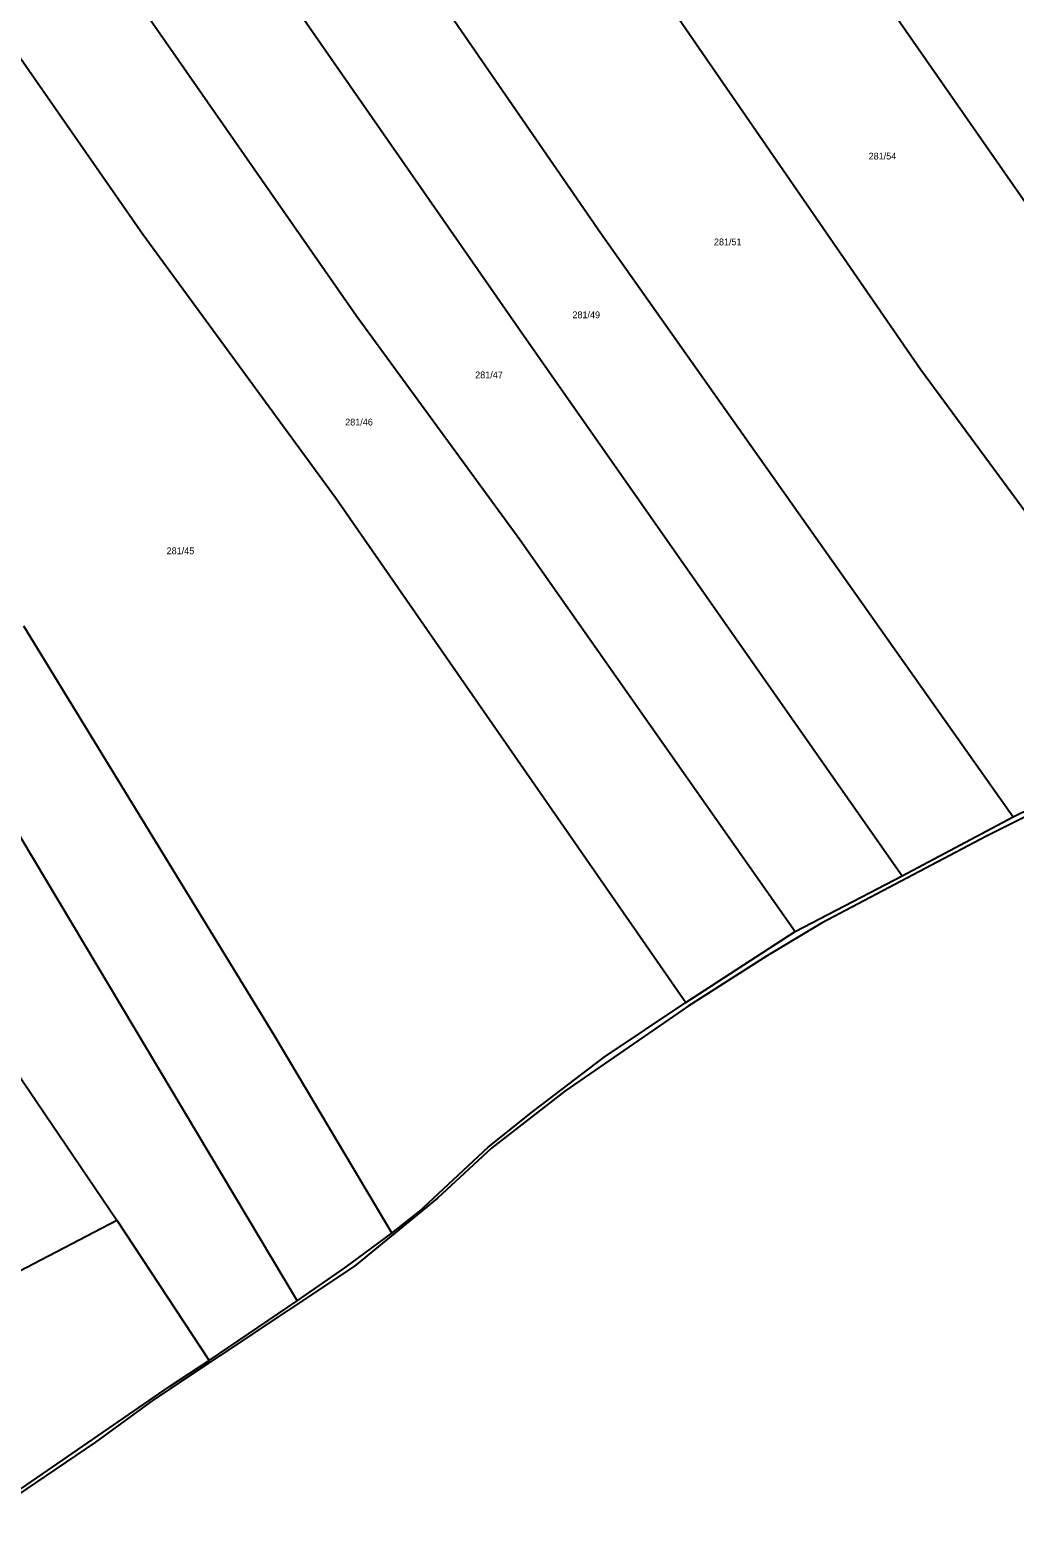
# Model space of a CAD drawing. Extents: x -779723 to -777378, y -1011169 to -1009297.
# Drawn here: x -778145.5 to -777897.6, y -1011100.8 to -1010721.1 of the extents above; entities that cross this region are included whole.
import ezdxf

# ---------------------------------------------------------------- set-up
doc = ezdxf.new("R2010")
doc.units = 0
doc.layers.add('KN_HRANICE', color=7, linetype='Continuous')
doc.layers.add('KN_PARCELY', color=7, linetype='Continuous')

msp = doc.modelspace()

# ---------------------------------------------------------------- linework, layer by layer
at = {"layer": 'KN_HRANICE'}
for p, q in [((-778087.99, -1010647.3), (-778001.85, -1010772.26)), ((-778115.74, -1010662.1), (-778021.13, -1010798.24)), ((-778143.85, -1010677.34), (-778063.35, -1010793.06)), ((-778173.03, -1010692.24), (-778117.21, -1010772.54)), ((-777935.33, -1010706.44), (-777864.34, -1010808.65)), ((-777983.83, -1010715.92), (-777921.4, -1010806.5)), ((-778117.21, -1010772.54), (-778068.65, -1010838.85)), ((-778001.85, -1010772.26), (-777898.07, -1010919.25)), ((-778063.35, -1010793.06), (-778022.29, -1010849.42)), ((-778021.13, -1010798.24), (-777926.01, -1010934.1)), ((-777921.4, -1010806.5), (-777893.7, -1010844.14)), ((-778068.65, -1010838.85), (-777980.49, -1010965.98)), ((-778022.29, -1010849.42), (-777952.91, -1010948.15)), ((-778147.23, -1010871.18), (-778084.18, -1010974.16)), ((-777898.07, -1010919.25), (-777855.82, -1010898.56)), ((-778156.55, -1010910.11), (-778078.29, -1011041.12)), ((-777893.68, -1010918.59), (-777904.75, -1010924.16)), ((-777926.01, -1010934.1), (-777898.07, -1010919.25)), ((-777904.75, -1010924.16), (-777946.29, -1010946.05)), ((-777952.91, -1010948.15), (-777926.01, -1010934.1)), ((-777980.49, -1010965.98), (-777952.91, -1010948.15)), ((-777946.29, -1010946.05), (-777960.11, -1010954.32)), ((-777960.11, -1010954.32), (-777979.84, -1010966.89)), ((-777979.84, -1010966.89), (-778010.92, -1010988.32)), ((-778001.04, -1010979.74), (-777980.49, -1010965.98)), ((-778084.18, -1010974.16), (-778054.46, -1011024.11)), ((-778150.99, -1010980.51), (-778123.71, -1011020.78)), ((-778018.96, -1010993.43), (-778001.04, -1010979.74)), ((-778010.92, -1010988.32), (-778029.41, -1011002.72)), ((-778030.19, -1011002.43), (-778018.96, -1010993.43)), ((-778047.71, -1011018.72), (-778030.19, -1011002.43)), ((-778029.41, -1011002.72), (-778042.94, -1011015.24)), ((-778042.94, -1011015.24), (-778063.87, -1011032.42)), ((-778232.23, -1011077.49), (-778123.71, -1011020.78)), ((-778123.71, -1011020.78), (-778100.49, -1011056.2)), ((-778054.46, -1011024.11), (-778047.71, -1011018.72)), ((-778066.28, -1011032.84), (-778054.46, -1011024.11)), ((-778063.87, -1011032.42), (-778114.5, -1011066.06)), ((-778078.29, -1011041.12), (-778066.28, -1011032.84)), ((-778100.49, -1011056.2), (-778078.29, -1011041.12)), ((-778110.44, -1011062.73), (-778100.49, -1011056.2)), ((-778164.52, -1011099.92), (-778110.44, -1011062.73)), ((-778114.5, -1011066.06), (-778129.05, -1011076.74)), ((-778129.05, -1011076.74), (-778164.73, -1011100.82))]:
    msp.add_line(p, q, dxfattribs=at)

# ---------------------------------------------------------------- texts
at = {"layer": 'KN_PARCELY'}
for s, p in [('281/54', (-777934.43, -1010753.71)), ('281/51', (-777973.38, -1010775.32)), ('281/49', (-778009.01, -1010793.69)), ('281/47', (-778033.49, -1010808.81)), ('281/46', (-778066.22, -1010820.7)), ('281/45', (-778111.18, -1010853.12))]:
    msp.add_text(s, height=1.7, dxfattribs=at).set_placement(p)

doc.saveas('drawing.dxf')
